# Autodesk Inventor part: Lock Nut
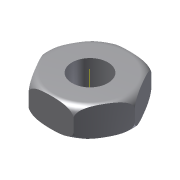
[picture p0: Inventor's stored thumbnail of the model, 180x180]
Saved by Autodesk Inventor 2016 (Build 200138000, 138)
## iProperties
Created: 2009-04
Part Number: Lock Nut
Document SubType Name: Modeling
Designer: Sham
Density: 1 g/cm^3
Material: Generic
Mass: 4.65064 g
Surface Area: 21.3319 cm^2
Volume: 4.65064 cm^3
Appearance: Default
Author: Sham
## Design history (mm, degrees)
sketch "Sketch1"
  geometry: L1 (7.5, 12.99)-(15, 0); L2 (15, 0)-(7.5, -12.99); L3 (7.5, -12.99)-(-7.5, -12.99); L4 (-7.5, -12.99)-(-15, 0); L5 (-15, 0)-(-7.5, 12.99); L6 (-7.5, 12.99)-(7.5, 12.99); C1 r 6 at (0, 0); 1 further point
  constraints: 12 end point, 1 centre point, 1 coincident, 13 other
  dimensions: "d0" = 30 distance of L1.end L4.end; "d1" = 12 diameter of C1
extrude "Extrusion1" new body sketch "Sketch1" distance "d2" = 10; taper "d3" = 0 deg
sketch "Sketch2"
  geometry: L1 (-12, 0)-(-12, -0.022); L2 (-15, 7)-(-15, 3); L3 (0, -2.87)-(0, 12.87) reference; A1 r 3 centre (-12, 7) between (-12, 10) and (-15, 7); A2 r 3 centre (-12, 3) between (-15, 3) and (-12, 0)
  constraints: 4 end point, 4 point on circle, 2 centre point, 1 tangent
revolve "Revolution1" sketch "Sketch2" stored, may be unused: angle "d7" = 90 deg
body "Solid1"
other parameters: "d6" = 90 deg
